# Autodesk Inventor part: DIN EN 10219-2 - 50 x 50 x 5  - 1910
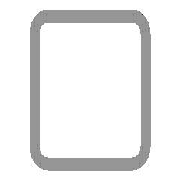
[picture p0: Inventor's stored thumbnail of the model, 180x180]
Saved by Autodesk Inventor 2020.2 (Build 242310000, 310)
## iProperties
IsCustomPart: 1
_CCFamilyMember: 16
_CCFamilyDisplayName: DIN EN 10219-2 (Quadratisches Hohlprofil - Kaltgeformt) - Kaltgeformte, geschweißte Baustahl-Hohlprofile aus unlegiertem Feinkorn-Baustahl
_FrameMemberDoc: Frame Member File
_Version: 15.0.0
_GetPNFromCC: 1
Created: 2019-01
Part Number: DIN EN 10219-2 - 50 x 50 x 5  - 1910
Material: Stahl, weich
Description: Kaltgeformte, geschweißte Baustahl-Hohlprofile aus unlegiertem Feinkorn-Baustahl
Document SubType Name: Modeling
Standard: DIN
Designer: lutzd
Standard Revision: 2006-07
Standards Organization: DIN
Language: de-DE
Size Designation: 50 x 50 x 5
Categories: <MemberInstance><Categories><Category DisplayName="Profile" InternalName="089c4875-fa83-4c05-b084-43b9cc11f5ed" Mnemonic="GRDR"><CategoryParameter DisplayName="
Stock Number: 50 x 50 x 5
Mass: 12501.6 g
Surface Area: 6407.85 cm^2
Volume: 1592.56 cm^3
Density: 7.85 g/cm^3
Appearance: Semi-Polished(8)
G_L: 1910,000 mm
G_W: 50,000 mm
G_H: 50,000 mm
DocNumber: ADSK-014381
Folder: .
Mass: 12,502 kg
VLT_Material: Stahl, weich
+4A8AB341-05B7-4827-B60A-4C9EF01C516A+SCHNITTDETAIL1: Schnittwinkel 90,00 grd
+C7A819A1-264E-4295-9BEB-65AA160B4128+SCHNITTDETAIL2: Schnittwinkel 90,00 grd
Dimensions: 50x50x1910 mm
Title: Profil-Bauteil
Author: lutzd
Revision Number: -
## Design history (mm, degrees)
node "Startebene"
node "Endebene"
sketch "Skizze"
  geometry: L1 (-25, -15)-(-25, 15); L2 (-15, 25)-(15, 25); L3 (25, 15)-(25, -15); L4 (15, -25)-(-15, -25); L5 (-15, 20)-(15, 20); L6 (20, 15)-(20, -15); L7 (15, -20)-(-15, -20); L8 (-20, -15)-(-20, 15); L9 (0, 37.899)-(0, -37.899) reference; L10 (-37.899, 0)-(37.899, 0) reference; A1 r 10 centre (-15, -15) between (-25, -15) and (-15, -25); A2 r 10 centre (-15, 15) between (-15, 25) and (-25, 15); A3 r 10 centre (15, 15) between (25, 15) and (15, 25); A4 r 10 centre (15, -15) between (15, -25) and (25, -15); A5 r 5 centre (-15, 15) between (-15, 20) and (-20, 15); A6 r 5 centre (15, 15) between (20, 15) and (15, 20); A7 r 5 centre (15, -15) between (15, -20) and (20, -15); A8 r 5 centre (-15, -15) between (-20, -15) and (-15, -20)
  constraints: 16 end point, 16 point on circle, 8 centre point, 8 tangent, 4 parallel, 3 equal radius, 2 perpendicular, 7 other
  dimensions: "d7" = 10 radius of A1 (= G_IR); "d10" = 50 distance between parallel lines of L2 L4 (= G_H); "d11" = 50 distance between parallel lines of L1 L3 (= G_W); "d12" = 5 distance between parallel lines of L3 L6 (= G_T); "d15" = 25 distance between parallel lines of L2 L10 (= 0.5 x d10); "d16" = 25 distance between parallel lines of L9 L3 (= 0.5 x d11)
extrude "Körper" new body sketch "Skizze" stored distance "d3" = 1910 (= G_L); taper "d4" = 0 deg
node "Driven Length"
  sketch "Sketch3"
    geometry: L1 (0, 0)-(10, 0) reference
    constraints: 2 end point, 1 horizontal
  workplane "Work Plane3"
  sketch "Sketch4"
    geometry: L1 (-2, 50)-(12, 50) reference; L2 (-2, 1960)-(12, 1960) reference
    dimensions: "d18" = 1910 distance between parallel lines of L1 L2 (derived)
workplane "Arbeitsebene4"
feature "Trennen1"
workplane "Arbeitsebene5"
feature "Trennen2"
sketch "Skizze5"
  geometry: L1 (30, 1910)-(0, 1910) reference; 17 further points
  constraints: 1 coincident, 1 midpoint, 16 other
  dimensions: "d19" = 1835 distance of point (15, 1910) point (15, 75); "d20" = 57 distance from line of L1 point (15, 1853); "d21" = 254 distance of point (15, 1599) point (15, 1853); "d22" = 254 distance of point (15, 1345) point (15, 1599) (= d21); "d23" = 254 distance of point (15, 1091) point (15, 1345) (= d21); "d24" = 254 distance of point (15, 837) point (15, 1091) (= d21); "d25" = 254 distance of point (15, 583) point (15, 837) (= d21); "d26" = 254 distance of point (15, 329) point (15, 583) (= d21); "d27" = 254 distance of point (15, 75) point (15, 329) (derived); "d35" = 70 distance of point (15, 130) point (15, 200); "d36" = 55 distance of point (15, 75) point (15, 130); "d44" = 90 distance of point (15, 515) point (15, 425); "d45" = 90 distance of point (15, 1378) point (15, 1288) (= d44); "d46" = 1485 distance from line of L1 point (15, 425); "d47" = 532 distance from line of L1 point (15, 1378)
hole "Bohrung1" sketch "Skizze5" diameter "d28" = 6.647; stored, may be unused: countersink angle "d32" = 90 deg, drill point angle "d34" = 118 deg; dims "d29" = 16, "d30" = 4, "d31" = 2, "d33" = 8
hole "Bohrung2" sketch "Skizze5" diameter "d37" = 6.647; stored, may be unused: countersink angle "d41" = 90 deg, drill point angle "d43" = 118 deg; dims "d38" = 16, "d39" = 4, "d40" = 2, "d42" = 8
body "Solid1"
other parameters: "G_W" = 50 [user parameter; used in 1 equation term], "G_H" = 50 [user parameter; used in 1 equation term], "G_T" = 5 [user parameter; used in 1 equation term], "G_IR" = 10 [user parameter; used in 1 equation term], "G_L" = 1910 (= d18) [user parameter; used in 1 equation term], "d17" = 90 deg
